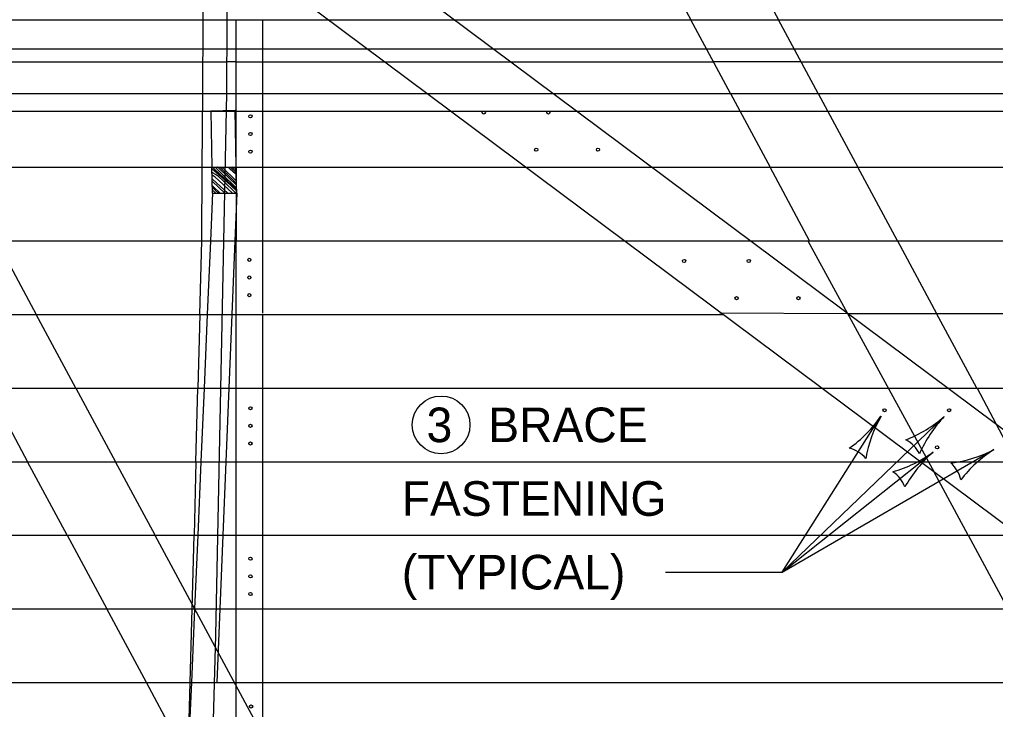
# Model space of a CAD drawing. Extents: x 49991.4 to 50021, y 49987.6 to 50011.4.
# Drawn here: x 50002.489 to 50004.182, y 49994.752 to 49995.949 of the extents above; entities that cross this region are included whole.
import ezdxf

# ---------------------------------------------------------------- set-up
doc = ezdxf.new("R2010")
doc.units = 0
for name, color, linetype in [('Level 1', 7, 'Continuous'), ('Level 2', 7, 'Continuous'), ('Level 3', 7, 'Continuous'), ('Level 4', 7, 'Continuous')]:
    doc.layers.add(name, color=color, linetype=linetype)

msp = doc.modelspace()

# ---------------------------------------------------------------- linework, layer by layer
at = {"layer": 'Level 1'}
for p, q in [((50004.8448, 49994.752), (50001.0146, 49997.6127)), ((50004.7604, 49994.652), (50000.9301, 49997.5128)), ((50000.6947, 49995.9482), (50003.0248, 49995.9482)), ((50002.8068, 49995.8204), (50002.8076, 49995.9482)), ((50002.8488, 49995.8204), (50002.8494, 49995.9482)), ((50002.865, 49995.8204), (50002.865, 49995.9482)), ((50002.9103, 49995.9482), (50002.9103, 49995.8204)), ((50003.2433, 49995.9482), (50005.0428, 49995.9482)), ((50003.7222, 49995.8204), (50003.6535, 49995.9482)), ((50003.8745, 49995.8204), (50003.8057, 49995.9482)), ((50002.2702, 49995.898), (50002.8073, 49995.898)), ((50002.8492, 49995.898), (50002.865, 49995.898)), ((50002.9103, 49995.898), (50003.092, 49995.898)), ((50003.3104, 49995.898), (50003.6805, 49995.898)), ((50003.8327, 49995.898), (50004.3275, 49995.898)), ((50002.2822, 49995.8757), (50002.8072, 49995.8757)), ((50002.865, 49995.8757), (50002.8491, 49995.8757)), ((50002.9103, 49995.8757), (50003.122, 49995.8757)), ((50003.3404, 49995.8757), (50003.6925, 49995.8757)), ((50003.8447, 49995.8757), (50004.3275, 49995.8757)), ((50000.6947, 49995.8204), (50003.1959, 49995.8204)), ((50003.4143, 49995.8204), (50005.0428, 49995.8204)), ((50000.6947, 49995.6928), (50003.367, 49995.6928)), ((50002.8054, 49995.565), (50002.806, 49995.6928)), ((50002.824, 49995.6478), (50002.8229, 49995.6928)), ((50002.8659, 49995.6478), (50002.8646, 49995.6928)), ((50002.865, 49995.6928), (50002.865, 49995.565)), ((50002.9103, 49995.6936), (50002.9103, 49995.565)), ((50003.5854, 49995.6928), (50005.0428, 49995.6928)), ((50003.8595, 49995.565), (50003.7909, 49995.6928)), ((50004.0119, 49995.565), (50003.9432, 49995.6928)), ((50002.824, 49995.6478), (50002.8203, 49995.565)), ((50002.824, 49995.6478), (50002.8659, 49995.6478)), ((50002.8659, 49995.6478), (50002.8626, 49995.565)), ((50000.6947, 49995.565), (50003.5379, 49995.565)), ((50003.7563, 49995.565), (50005.0428, 49995.565)), ((50000.6947, 49995.4372), (50003.709, 49995.4372)), ((50002.5868, 49995.3094), (50002.5181, 49995.4372)), ((50002.802, 49995.4372), (50002.7986, 49995.3094)), ((50002.8148, 49995.4372), (50002.8094, 49995.3094)), ((50002.8574, 49995.4372), (50002.8522, 49995.3094)), ((50002.865, 49995.3094), (50002.865, 49995.4372)), ((50002.9103, 49995.4372), (50002.9103, 49995.3094)), ((50003.9254, 49995.4386), (50005.0428, 49995.4386)), ((50004.1494, 49995.3094), (50004.0799, 49995.4386)), ((50000.6947, 49995.3094), (50003.8801, 49995.3094)), ((50004.0985, 49995.3094), (50005.0428, 49995.3094)), ((50000.6947, 49995.1816), (50004.0512, 49995.1816)), ((50002.5719, 49995.054), (50002.5032, 49995.1816)), ((50002.7242, 49995.054), (50002.6555, 49995.1816)), ((50002.7951, 49995.1816), (50002.7918, 49995.054)), ((50002.8038, 49995.1816), (50002.7982, 49995.054)), ((50002.847, 49995.1816), (50002.8418, 49995.054)), ((50002.865, 49995.054), (50002.865, 49995.1816)), ((50002.9103, 49995.1816), (50002.9103, 49995.054)), ((50003.9413, 49995.1816), (50003.9886, 49995.1816)), ((50004.1346, 49995.054), (50004.0757, 49995.1634)), ((50000.6947, 49995.054), (50004.2222, 49995.054)), ((50000.6947, 49994.9262), (50004.3933, 49994.9262)), ((50002.7094, 49994.7984), (50002.6406, 49994.9262)), ((50002.7851, 49994.7984), (50002.7885, 49994.9262)), ((50002.7928, 49994.9262), (50002.7872, 49994.7984)), ((50002.8366, 49994.9262), (50002.8312, 49994.7984)), ((50002.865, 49994.7984), (50002.865, 49994.9262)), ((50002.9103, 49994.9262), (50002.9103, 49994.7984)), ((50000.6947, 49994.7984), (50004.5643, 49994.7984))]:
    msp.add_line(p, q, dxfattribs=at)
for points in [[(50002.865, 49995.6519), (50002.8479, 49995.6677), (50002.8356, 49995.6786), (50002.8233, 49995.6889), (50002.823, 49995.6893)], [(50002.8649, 49995.6545), (50002.8492, 49995.6688), (50002.837, 49995.6799), (50002.8268, 49995.6896), (50002.8237, 49995.6929)], [(50002.8649, 49995.6569), (50002.8579, 49995.6635), (50002.847, 49995.6742), (50002.8328, 49995.6886), (50002.8284, 49995.6928)], [(50002.8649, 49995.662), (50002.8516, 49995.675), (50002.833, 49995.6926), (50002.8328, 49995.6928)], [(50002.8649, 49995.665), (50002.8576, 49995.6726), (50002.8365, 49995.6928)], [(50002.8649, 49995.6692), (50002.8585, 49995.6755), (50002.8463, 49995.6867), (50002.84, 49995.6928)], [(50002.865, 49995.6799), (50002.8639, 49995.6811), (50002.8544, 49995.6894), (50002.851, 49995.6929)], [(50002.8648, 49995.6841), (50002.864, 49995.6848), (50002.8552, 49995.6927)], [(50002.8648, 49995.6869), (50002.8596, 49995.6917), (50002.8585, 49995.693)], [(50002.8641, 49995.6476), (50002.8429, 49995.6681), (50002.8342, 49995.6764), (50002.8289, 49995.6802), (50002.8251, 49995.6822), (50002.8232, 49995.6841)], [(50002.8586, 49995.6477), (50002.835, 49995.6695), (50002.8286, 49995.6751), (50002.8233, 49995.679)], [(50002.8505, 49995.6478), (50002.8307, 49995.6655), (50002.8234, 49995.6726)], [(50002.8453, 49995.6478), (50002.8236, 49995.6678), (50002.8236, 49995.6678)], [(50002.8371, 49995.6478), (50002.8249, 49995.6591), (50002.8236, 49995.6604)], [(50002.8341, 49995.6478), (50002.8292, 49995.6522), (50002.8237, 49995.6572)], [(50002.8644, 49995.6549), (50002.8644, 49995.6549)], [(50002.8298, 49995.6478), (50002.8292, 49995.6484), (50002.8238, 49995.653)]]:
    msp.add_lwpolyline(points, dxfattribs=at)
for centre in [(50003.2943, 49995.7874), (50003.4064, 49995.7874), (50002.8897, 49995.7809), (50002.8897, 49995.7502), (50002.8897, 49995.7196), (50003.3854, 49995.7229), (50003.4925, 49995.7229), (50002.8877, 49995.5319), (50003.6419, 49995.5299), (50003.754, 49995.5299), (50002.8877, 49995.5012), (50002.8877, 49995.4706), (50003.733, 49995.4654), (50003.8401, 49995.4654), (50002.8897, 49995.2744), (50003.9895, 49995.2709), (50004.1016, 49995.2709), (50002.8897, 49995.2438), (50002.8897, 49995.2131), (50004.0806, 49995.2065), (50002.8897, 49995.0133), (50002.8897, 49994.9826), (50002.8897, 49994.952), (50002.8907, 49994.7568)]:
    msp.add_ellipse(centre, major_axis=(0.00285, 0), ratio=0.940299, dxfattribs=at)
at = {"layer": 'Level 2'}
msp.add_circle((50003.2204, 49995.2455), 0.05, dxfattribs=at)
at = {"layer": 'Level 3'}
for p, q in [((50003.8121, 49994.9899), (50003.9834, 49995.2604)), ((50003.8121, 49994.9899), (50004.0932, 49995.2602)), ((50003.8121, 49994.9899), (50004.1791, 49995.2026)), ((50003.8121, 49994.9899), (50004.0739, 49995.1983)), ((50003.6098, 49994.9899), (50003.8121, 49994.9899))]:
    msp.add_line(p, q, dxfattribs=at)
for centre, radius, start, end in [((50003.8006, 49995.387), 0.2223, 305.1111, 325.2946), ((50004.1862, 49995.1456), 0.233, 150.4824, 169.7322), ((50003.9458, 49995.4267), 0.2223, 291.3339, 311.5174), ((50004.2628, 49995.1004), 0.233, 136.7052, 155.9551), ((50004.0008, 49995.1713), 0.0548, 26.0167, 61.7391), ((50003.9148, 49995.1521), 0.0548, 39.7939, 75.5163), ((50003.9427, 49995.3778), 0.2223, 285.9768, 306.1603), ((50004.2278, 49995.0234), 0.233, 131.3481, 150.5979), ((50004.0756, 49995.3994), 0.2223, 277.5511, 297.7346), ((50004.3057, 49995.007), 0.233, 122.9224, 142.1722), ((50003.9736, 49995.1184), 0.0548, 20.6596, 56.3819), ((50004.0682, 49995.1383), 0.0548, 12.2339, 47.9562)]:
    msp.add_arc(centre, radius, start, end, dxfattribs=at)
at = {"layer": 'Level 4'}
for p, q in [((50002.8076, 49995.9482), (50002.8084, 49996.076)), ((50002.8494, 49995.9482), (50002.8501, 49996.076)), ((50003.5848, 49996.076), (50003.6535, 49995.9482)), ((50003.7371, 49996.076), (50003.8057, 49995.9482)), ((50003.0248, 49995.9482), (50003.2433, 49995.9482)), ((50002.8073, 49995.898), (50002.8492, 49995.898)), ((50002.865, 49995.898), (50002.9103, 49995.898)), ((50003.092, 49995.898), (50003.3104, 49995.898)), ((50003.6805, 49995.898), (50003.8327, 49995.898)), ((50002.8072, 49995.8757), (50002.8491, 49995.8757)), ((50002.865, 49995.8757), (50002.9103, 49995.8757)), ((50003.122, 49995.8757), (50003.3404, 49995.8757)), ((50003.8447, 49995.8757), (50003.6925, 49995.8757)), ((50002.806, 49995.6928), (50002.8068, 49995.8204)), ((50002.8294, 49994.8804), (50002.8488, 49995.8204)), ((50002.865, 49995.6928), (50002.865, 49995.8187)), ((50002.9103, 49995.8194), (50002.9103, 49995.6936)), ((50003.1959, 49995.8204), (50003.4143, 49995.8204)), ((50003.7222, 49995.8204), (50003.7909, 49995.6928)), ((50003.8745, 49995.8204), (50003.9432, 49995.6928)), ((50001.2572, 49995.7899), (50004.4313, 49995.7899)), ((50002.863, 49995.7908), (50002.821, 49995.7899)), ((50002.821, 49995.7899), (50002.8229, 49995.6928)), ((50002.865, 49995.6946), (50002.863, 49995.7908)), ((50003.367, 49995.6928), (50003.5854, 49995.6928)), ((50002.4493, 49995.565), (50002.5181, 49995.4372)), ((50002.802, 49995.4372), (50002.8054, 49995.565)), ((50002.8204, 49995.565), (50002.8148, 49995.4372)), ((50002.8627, 49995.565), (50002.8574, 49995.4372)), ((50002.865, 49995.4382), (50002.865, 49995.565)), ((50002.9103, 49995.565), (50002.9103, 49995.4393)), ((50003.5379, 49995.565), (50003.7563, 49995.565)), ((50003.8565, 49995.565), (50004.0757, 49995.1634)), ((50004.0119, 49995.565), (50004.0799, 49995.4386)), ((50003.704, 49995.44), (50003.9254, 49995.4386)), ((50002.4345, 49995.3094), (50002.5032, 49995.1816)), ((50002.5868, 49995.3094), (50002.6555, 49995.1816)), ((50002.7951, 49995.1816), (50002.7986, 49995.3094)), ((50002.8093, 49995.3094), (50002.8038, 49995.1816)), ((50002.8522, 49995.3094), (50002.847, 49995.1816)), ((50002.865, 49995.1816), (50002.865, 49995.3094)), ((50002.9103, 49995.3094), (50002.9103, 49995.1816)), ((50003.8801, 49995.3094), (50004.0985, 49995.3094)), ((50004.1502, 49995.3094), (50004.3516, 49994.9262)), ((50004.0512, 49995.1816), (50004.2696, 49995.1816)), ((50002.5719, 49995.054), (50002.6406, 49994.9262)), ((50002.7241, 49995.054), (50002.9306, 49994.6706)), ((50002.7885, 49994.9262), (50002.7918, 49995.054)), ((50002.7982, 49995.054), (50002.7928, 49994.9262)), ((50002.8418, 49995.054), (50002.8366, 49994.9262)), ((50002.865, 49994.9262), (50002.865, 49995.054)), ((50002.9103, 49995.054), (50002.9103, 49994.9269)), ((50004.1346, 49995.054), (50004.2032, 49994.9262)), ((50002.8238, 49994.6706), (50002.8294, 49994.8804)), ((50002.865, 49994.6706), (50002.865, 49994.8246)), ((50002.8648, 49994.5096), (50002.7094, 49994.7984)), ((50002.7872, 49994.7984), (50002.7817, 49994.6706)), ((50002.7817, 49994.6706), (50002.7851, 49994.7984)), ((50002.9103, 49994.7984), (50002.9103, 49994.651))]:
    msp.add_line(p, q, dxfattribs=at)

# ---------------------------------------------------------------- texts
at = {"layer": 'Level 2'}
for s, p in [('3', (50003.1951, 49995.2155)), ('BRACE', (50003.3021, 49995.2155)), ('FASTENING', (50003.1521, 49995.0877)), ('(TYPICAL)', (50003.1522, 49994.9599))]:
    msp.add_text(s, height=0.06, dxfattribs=at).set_placement(p)

doc.saveas('drawing.dxf')
